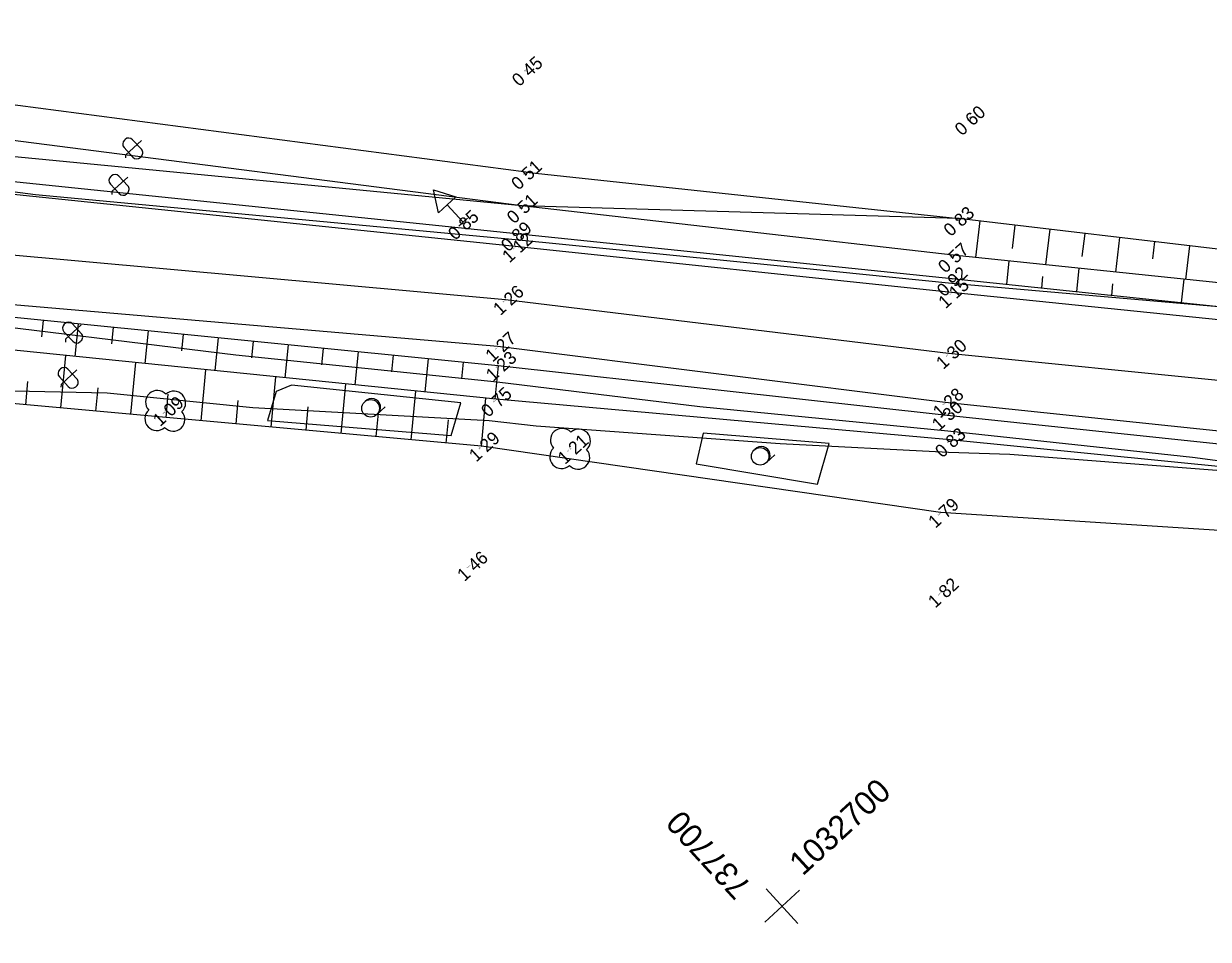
# Model space of a CAD drawing. Extents: x -740053 to -737481, y -1033516 to -1032488.
# Drawn here: x -737847.6 to -737797.1, y -1032916.2 to -1032877.2 of the extents above; entities that cross this region are included whole.
import ezdxf

# ---------------------------------------------------------------- set-up
doc = ezdxf.new("R2010")
doc.units = 0
for name, color, linetype in [('bod-oznac', 7, 'Continuous'), ('bod-vyska', 7, 'Continuous'), ('bod-vyska100', 7, 'Continuous'), ('Contours', 7, 'Continuous'), ('ctv-sit', 7, 'Continuous'), ('dopr-zariz', 7, 'Continuous'), ('Hranice-zelene', 7, 'Continuous'), ('osa-komunikace', 7, 'Continuous'), ('rozhraní kultůr', 7, 'Continuous'), ('silnice', 7, 'Continuous'), ('Technické šrafy', 7, 'Continuous'), ('Terenni-hrana', 7, 'Continuous'), ('Znacky-kultury', 7, 'Continuous')]:
    doc.layers.add(name, color=color, linetype=linetype)

# ---------------------------------------------------------------- blocks, each defined once
blk = doc.blocks.new('d_znacka')
for p, q in [((-1, 2), (0, 3.73)), ((0, 3.73), (1, 2)), ((-1, 2), (1, 2)), ((0, 0), (0, 2)), ((-0.5, 0), (0.5, 0))]:
    blk.add_line(p, q)
blk = doc.blocks.new('POINT_DISPLAY')
blk.add_line((0, 0), (0, 0))
blk = doc.blocks.new('p_strom')
for centre, start, end in [((0, 1), 0, 180), ((-1, 0), 90, 270), ((1, 0), 270, 90), ((0, -1), 180, 0)]:
    blk.add_arc(centre, 1, start, end)
at = {"rotation": -180}
blk.add_blockref('POINT_DISPLAY', (0, 0), dxfattribs=at)
blk = doc.blocks.new('p_neplod')
for p, q in [((-0.82, 0), (-0.99, -0.18)), ((1, 0), (-0.82, 0)), ((-0.49, 0.56), (-0.49, -0.55)), ((0.05, 1.01), (-0.04, 1.01)), ((0.5, -0.55), (0.5, 0.56)), ((-0.04, -1), (0.05, -1))]:
    blk.add_line(p, q)
for centre, start, end in [((-0.04, 0.56), 90, 180), ((0.05, 0.56), 0, 90), ((-0.04, -0.55), 180, 270), ((0.05, -0.55), 270, 0)]:
    blk.add_arc(centre, 0.45, start, end)
blk = doc.blocks.new('p_leskro')
blk.add_line((0, -0.75), (1, -0.75))
blk.add_circle((0, 0), 0.75)
blk.add_arc((0.13, 0), 0.75, 264.8832, 95.1168)
blk = doc.blocks.new('ctvsit')
for p, q in [((0, -2), (0, 2)), ((2, 0), (-2, 0))]:
    blk.add_line(p, q)

msp = doc.modelspace()

# ---------------------------------------------------------------- linework, layer by layer
at = {"layer": 'Contours'}
for points in [[(-737796.34, -1032889.277), (-737808.036, -1032888.253), (-737815.475, -1032887.503), (-737826.627, -1032886.393), (-737847.092, -1032884.477), (-737850.825, -1032883.994), (-737858.487, -1032883.105), (-737869.917, -1032882.163), (-737877.56, -1032881.438), (-737878.192, -1032881.565), (-737878.849, -1032881.569), (-737893.527, -1032879.618), (-737890.546, -1032878.973), (-737891.082, -1032877.779), (-737893.05, -1032877.402), (-737895.298, -1032877.178)], [(-737851.121, -1032889.756), (-737838.556, -1032891.298), (-737827.412, -1032892.443), (-737818.776, -1032893.496), (-737808.196, -1032894.535), (-737797.769, -1032895.651), (-737789.023, -1032896.821), (-737805.559, -1032895.546), (-737808.176, -1032895.463), (-737815.352, -1032895.086), (-737825.745, -1032894.334), (-737827.75, -1032894.113), (-737837.83, -1032893.55), (-737844.041, -1032892.935), (-737851.352, -1032892.765)]]:
    msp.add_lwpolyline(points, dxfattribs=at)
at = {"layer": 'Hranice-zelene'}
for points in [[(-737836.834, -1032892.857), (-737837.203, -1032894.092), (-737829.373, -1032894.727), (-737828.97, -1032893.343), (-737836.176, -1032892.593), (-737836.834, -1032892.857)], [(-737818.634, -1032894.631), (-737818.924, -1032895.939), (-737813.756, -1032896.806), (-737813.254, -1032895.072), (-737818.634, -1032894.631)]]:
    msp.add_lwpolyline(points, dxfattribs=at)
at = {"layer": 'osa-komunikace'}
for p, q in [((-737827.061, -1032888.949), (-737851.201, -1032886.757)), ((-737808.176, -1032891.244), (-737827.061, -1032888.949)), ((-737777.743, -1032894.266), (-737808.176, -1032891.244))]:
    msp.add_line(p, q, dxfattribs=at)
at = {"layer": 'rozhraní kultůr'}
for q in [(-737849.703, -1032880.423), (-737807.742, -1032885.48)]:
    msp.add_line((-737826.173, -1032883.501), q, dxfattribs=at)
at = {"layer": 'silnice'}
for p, q in [((-737826.647, -1032886.68), (-737850.817, -1032884.176)), ((-737808.052, -1032888.631), (-737826.647, -1032886.68)), ((-737827.392, -1032890.938), (-737851.347, -1032888.875)), ((-737777.419, -1032891.767), (-737808.052, -1032888.631)), ((-737808.313, -1032893.326), (-737827.392, -1032890.938)), ((-737777.788, -1032896.508), (-737808.313, -1032893.326))]:
    msp.add_line(p, q, dxfattribs=at)
at = {"layer": 'Technické šrafy'}
for p, q in [((-737806.837, -1032885.587), (-737807.021, -1032887.142)), ((-737805.347, -1032885.764), (-737805.465, -1032886.757)), ((-737803.858, -1032885.94), (-737804.037, -1032887.454)), ((-737802.368, -1032886.116), (-737802.486, -1032887.109)), ((-737800.879, -1032886.293), (-737801.053, -1032887.767)), ((-737799.389, -1032886.469), (-737799.475, -1032887.196)), ((-737797.899, -1032886.646), (-737798.069, -1032888.08)), ((-737805.693, -1032888.296), (-737805.587, -1032887.292)), ((-737802.709, -1032888.609), (-737802.604, -1032887.605)), ((-737804.201, -1032888.452), (-737804.148, -1032887.95)), ((-737801.217, -1032888.765), (-737801.165, -1032888.263)), ((-737798.234, -1032889.078), (-737798.128, -1032888.074)), ((-737846.775, -1032889.831), (-737846.843, -1032890.522)), ((-737845.282, -1032889.979), (-737845.419, -1032891.364)), ((-737843.789, -1032890.128), (-737843.858, -1032890.821)), ((-737842.297, -1032890.276), (-737842.435, -1032891.666)), ((-737840.804, -1032890.424), (-737840.873, -1032891.121)), ((-737839.311, -1032890.573), (-737839.45, -1032891.969)), ((-737837.819, -1032890.721), (-737837.888, -1032891.421)), ((-737836.326, -1032890.869), (-737836.465, -1032892.272)), ((-737846.014, -1032893.558), (-737845.81, -1032891.324)), ((-737834.833, -1032891.018), (-737834.903, -1032891.72)), ((-737833.341, -1032891.166), (-737833.481, -1032892.575)), ((-737831.848, -1032891.314), (-737831.918, -1032892.02)), ((-737843.026, -1032893.83), (-737842.825, -1032891.627)), ((-737830.355, -1032891.463), (-737830.496, -1032892.877)), ((-737828.863, -1032891.611), (-737828.933, -1032892.32)), ((-737827.37, -1032891.759), (-737827.511, -1032893.18)), ((-737847.507, -1032893.422), (-737847.417, -1032892.426)), ((-737840.038, -1032894.102), (-737839.841, -1032891.93)), ((-737837.051, -1032894.374), (-737836.856, -1032892.232)), ((-737844.52, -1032893.694), (-737844.429, -1032892.698)), ((-737834.063, -1032894.646), (-737833.871, -1032892.535)), ((-737831.075, -1032894.918), (-737830.886, -1032892.838)), ((-737841.532, -1032893.966), (-737841.442, -1032892.97)), ((-737838.545, -1032894.238), (-737838.454, -1032893.242)), ((-737828.088, -1032895.19), (-737827.901, -1032893.14)), ((-737835.557, -1032894.51), (-737835.466, -1032893.514)), ((-737832.569, -1032894.782), (-737832.479, -1032893.786)), ((-737829.582, -1032895.054), (-737829.491, -1032894.058))]:
    msp.add_line(p, q, dxfattribs=at)
at = {"layer": 'Terenni-hrana'}
for p, q in [((-737826.361, -1032884.937), (-737849.52, -1032881.966)), ((-737826.361, -1032884.937), (-737850.806, -1032882.577)), ((-737826.609, -1032886.13), (-737850.843, -1032883.63)), ((-737807.978, -1032887.041), (-737826.361, -1032884.937)), ((-737807.742, -1032885.48), (-737826.361, -1032884.937)), ((-737777.045, -1032889.115), (-737807.742, -1032885.48)), ((-737808.027, -1032888.051), (-737826.609, -1032886.13)), ((-737777.179, -1032890.27), (-737807.978, -1032887.041)), ((-737777.348, -1032891.268), (-737808.027, -1032888.051)), ((-737827.37, -1032891.759), (-737851.093, -1032889.402)), ((-737827.458, -1032893.185), (-737851.201, -1032890.777)), ((-737808.357, -1032893.869), (-737827.37, -1032891.759)), ((-737828.088, -1032895.19), (-737851.375, -1032893.07)), ((-737808.104, -1032894.913), (-737827.458, -1032893.185)), ((-737777.706, -1032897.084), (-737808.357, -1032893.869)), ((-737777.799, -1032897.944), (-737808.104, -1032894.913)), ((-737808.511, -1032898.017), (-737828.088, -1032895.19)), ((-737777.539, -1032900), (-737808.511, -1032898.017))]:
    msp.add_line(p, q, dxfattribs=at)

# ---------------------------------------------------------------- block references
at = {"layer": 'bod-oznac', "rotation": 42.589429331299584}
for p in [(-737826.143, -1032879.086), (-737807.257, -1032881.176), (-737826.173, -1032883.501), (-737826.361, -1032884.937), (-737828.868, -1032885.638), (-737807.742, -1032885.48), (-737826.609, -1032886.13), (-737826.647, -1032886.68), (-737807.978, -1032887.041), (-737808.027, -1032888.051), (-737808.052, -1032888.631), (-737827.061, -1032888.949), (-737827.392, -1032890.938), (-737808.176, -1032891.244), (-737827.37, -1032891.759), (-737827.458, -1032893.185), (-737808.313, -1032893.326), (-737841.563, -1032893.681), (-737808.357, -1032893.869), (-737808.104, -1032894.913), (-737828.088, -1032895.19), (-737824.306, -1032895.3), (-737808.511, -1032898.017), (-737828.592, -1032900.286), (-737808.519, -1032901.421)]:
    msp.add_blockref('POINT_DISPLAY', p, dxfattribs=at)
at = {"layer": 'ctv-sit', "xscale": 0.49999999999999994, "yscale": 0.49999999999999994, "rotation": -137.41057066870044}
msp.add_blockref('ctvsit', (-737815.268, -1032914.796), dxfattribs=at)
at = {"layer": 'dopr-zariz', "xscale": 0.4999999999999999, "yscale": 0.49999999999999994, "rotation": 42.58942933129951}
msp.add_blockref('d_znacka', (-737828.868, -1032885.638), dxfattribs=at)
at = {"layer": 'Znacky-kultury', "yscale": 0.49999999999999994}
for name, p, xscale, rotation in [('p_neplod', (-737842.951, -1032882.5), 0.49999999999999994, 42.589429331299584), ('p_neplod', (-737843.535, -1032884.053), 0.49999999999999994, 42.589429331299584), ('p_neplod', (-737845.514, -1032890.349), 0.49999999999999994, 42.589429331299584), ('p_neplod', (-737845.707, -1032892.277), 0.49999999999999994, 42.589429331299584), ('p_strom', (-737841.563, -1032893.681), 0.4999999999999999, 42.58942933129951), ('p_leskro', (-737832.811, -1032893.573), 0.49999999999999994, 42.589429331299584), ('p_strom', (-737824.306, -1032895.3), 0.4999999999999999, 42.58942933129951), ('p_leskro', (-737816.201, -1032895.621), 0.49999999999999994, 42.589429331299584)]:
    msp.add_blockref(name, p, dxfattribs=dict(at, xscale=xscale, rotation=rotation))

# ---------------------------------------------------------------- texts
at = {"layer": 'bod-vyska'}
for s, p in [('0 45', (-737826.476, -1032879.89)), ('0 60', (-737807.599, -1032881.989)), ('0 51', (-737826.506, -1032884.305)), ('0 51', (-737826.694, -1032885.741)), ('0 85', (-737829.2, -1032886.442)), ('0 83', (-737808.075, -1032886.284)), ('0 89', (-737826.942, -1032886.933)), ('1 12', (-737826.893, -1032887.404)), ('0 57', (-737808.31, -1032887.845)), ('0 92', (-737808.36, -1032888.855)), ('1 26', (-737827.278, -1032889.646)), ('1 15', (-737808.298, -1032889.355)), ('1 27', (-737827.609, -1032891.635)), ('1 30', (-737808.393, -1032891.942)), ('1 23', (-737827.587, -1032892.457)), ('0 75', (-737827.791, -1032893.989)), ('1 28', (-737808.53, -1032894.024)), ('1 09', (-737841.78, -1032894.379)), ('1 30', (-737808.574, -1032894.567)), ('0 83', (-737808.437, -1032895.717)), ('1 29', (-737828.305, -1032895.888)), ('1 21', (-737824.523, -1032895.997)), ('1 79', (-737808.728, -1032898.715)), ('1 46', (-737828.809, -1032900.983)), ('1 82', (-737808.736, -1032902.118))]:
    msp.add_text(s, height=0.55, rotation=42.5894, dxfattribs=at).set_placement(p)
at = {"layer": 'bod-vyska100'}
for s, p in [('250 45', (-737826.243, -1032879.224)), ('250 60', (-737807.358, -1032881.315)), ('250 51', (-737826.274, -1032883.639)), ('250 51', (-737826.461, -1032885.074)), ('250 85', (-737828.968, -1032885.776)), ('250 83', (-737807.843, -1032885.618)), ('250 89', (-737826.71, -1032886.267)), ('251 12', (-737826.744, -1032886.815)), ('250 57', (-737808.078, -1032887.179)), ('250 92', (-737808.128, -1032888.189)), ('251 15', (-737808.149, -1032888.766)), ('251 26', (-737827.156, -1032889.081)), ('251 27', (-737827.487, -1032891.07)), ('251 30', (-737808.271, -1032891.377)), ('251 23', (-737827.465, -1032891.892)), ('250 75', (-737827.559, -1032893.323)), ('251 28', (-737808.408, -1032893.459)), ('251 09', (-737841.658, -1032893.814)), ('251 30', (-737808.452, -1032894.002)), ('250 83', (-737808.204, -1032895.051)), ('251 29', (-737828.183, -1032895.323)), ('251 21', (-737824.401, -1032895.432)), ('251 79', (-737808.606, -1032898.15)), ('251 46', (-737828.688, -1032900.418)), ('251 82', (-737808.614, -1032901.554))]:
    msp.add_text(s, height=0.05, rotation=42.5894, dxfattribs=at).set_placement(p)
at = {"layer": 'ctv-sit'}
for s, rotation, p in [('1032700', 42.5894, (-737814.389, -1032913.535)), ('737700', 132.5894, (-737816.529, -1032913.917))]:
    msp.add_text(s, height=1, rotation=rotation, dxfattribs=at).set_placement(p)

doc.saveas('drawing.dxf')
